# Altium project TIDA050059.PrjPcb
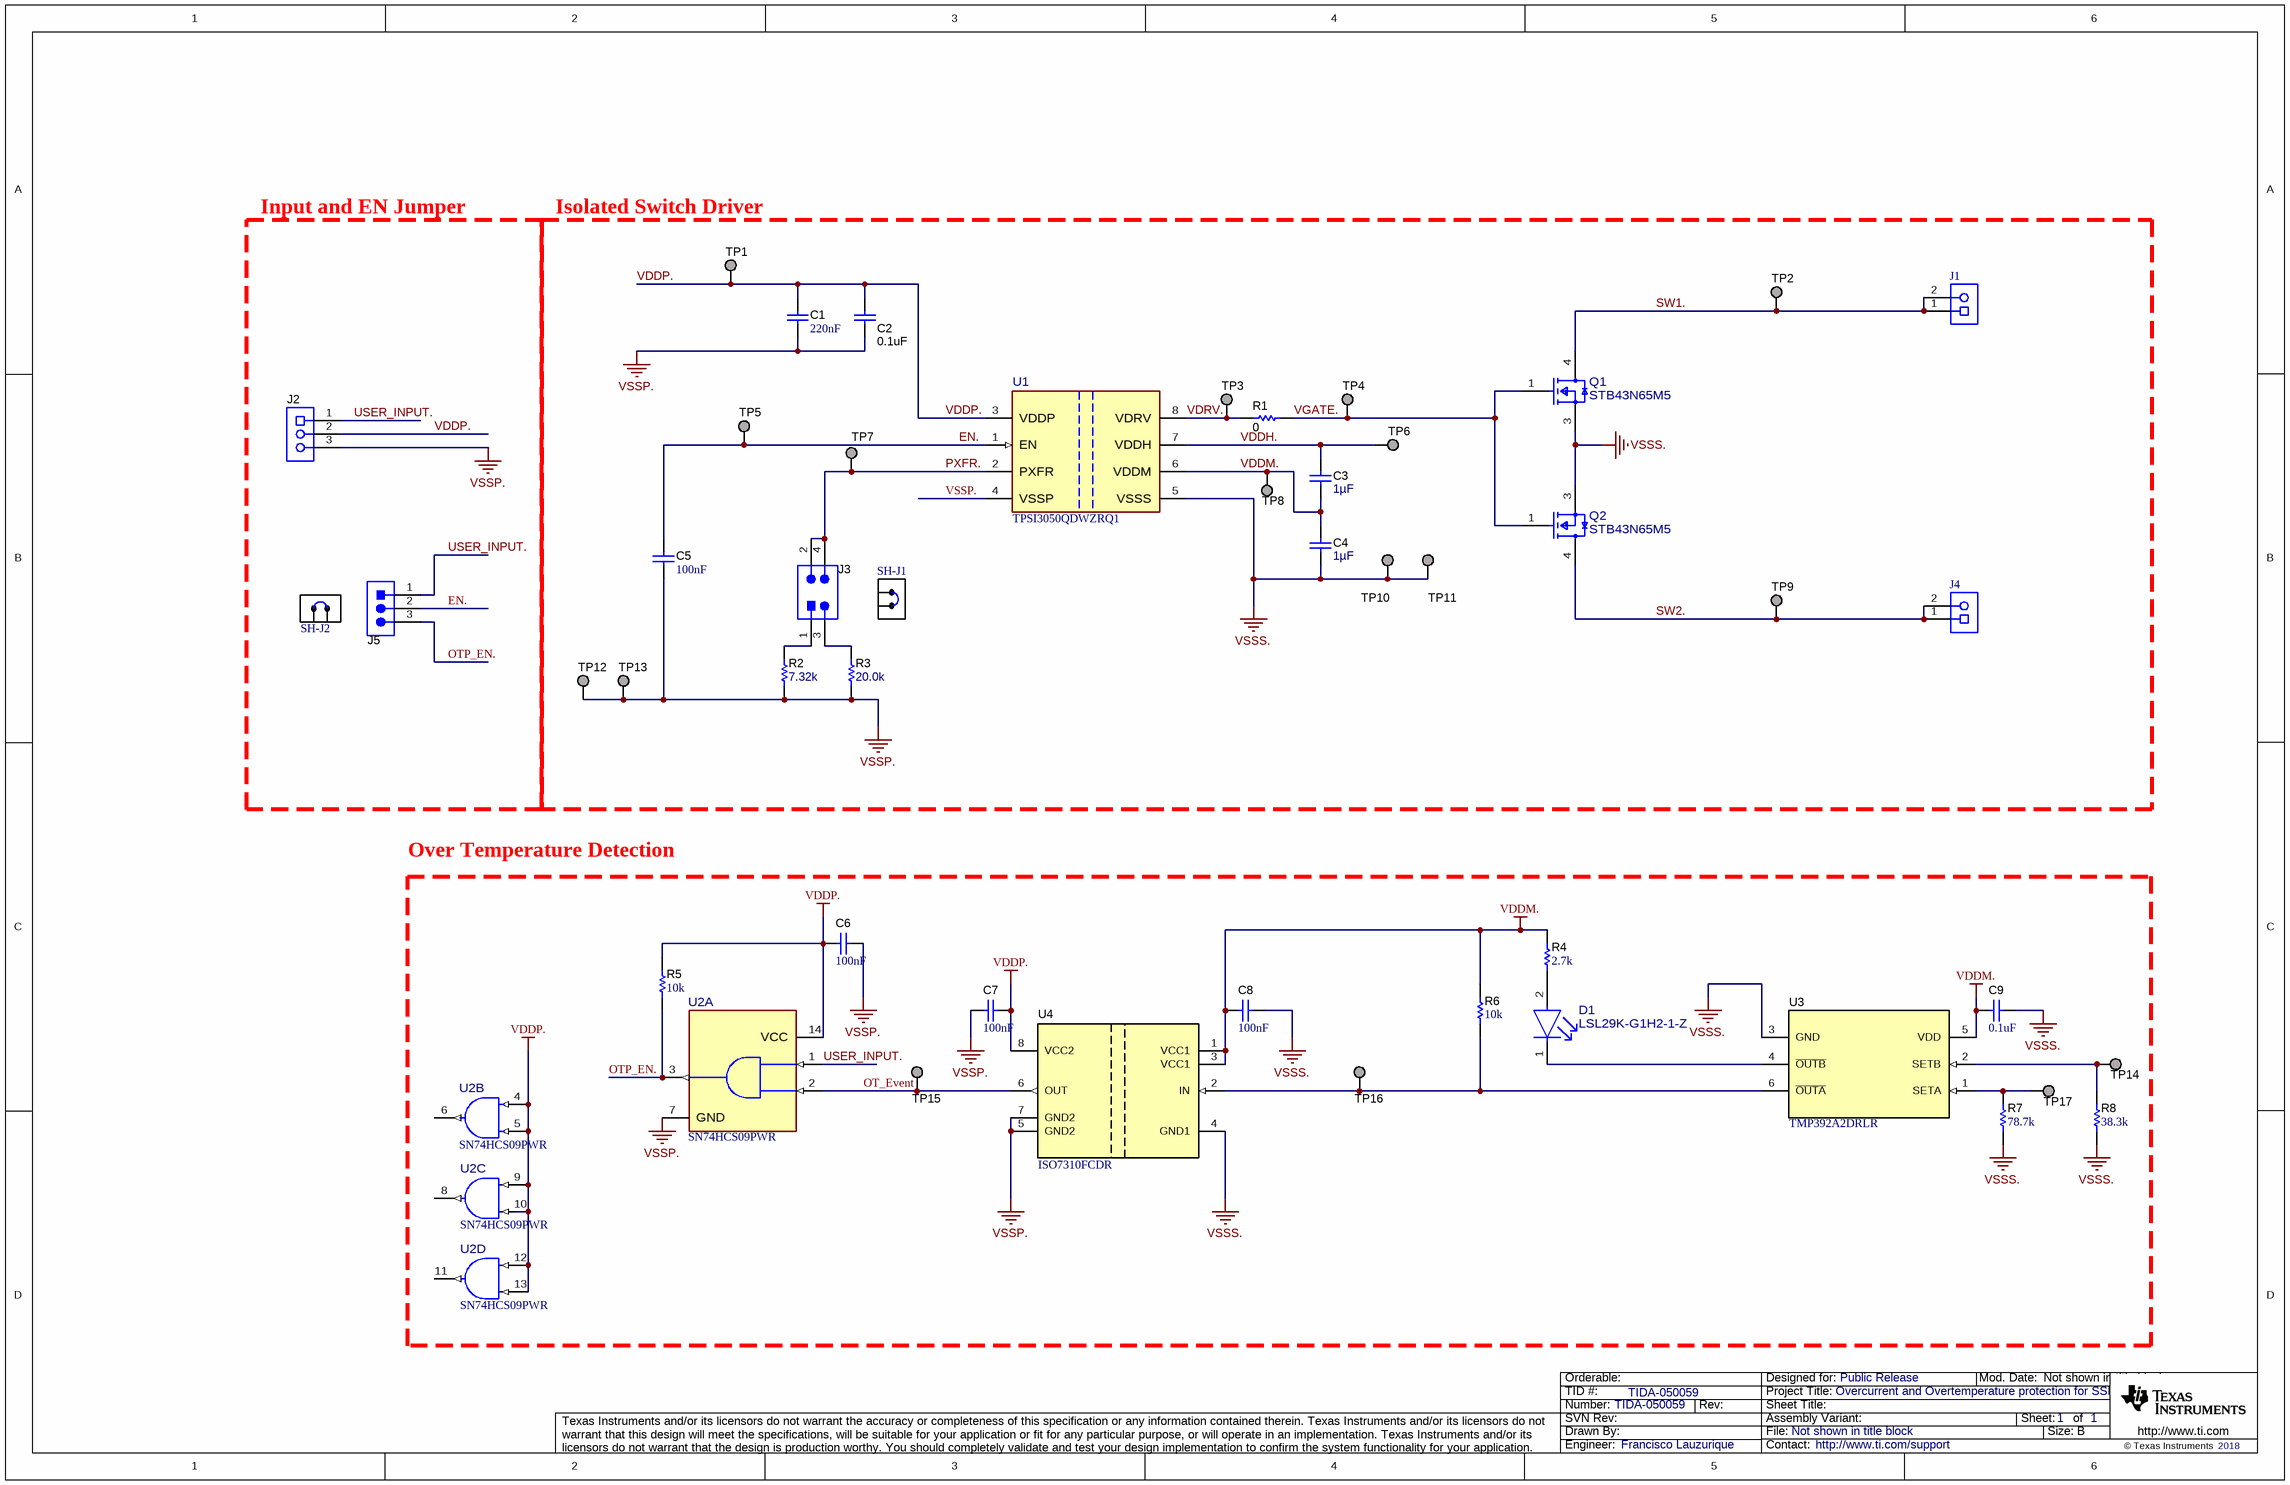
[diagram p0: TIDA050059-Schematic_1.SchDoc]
TID: TIDA-050059; TechSupport: http://www.ti.com/support; PRJ_Title: Overcurrent and Overtemperature protection for SSR; PRJ_Number: TIDA-050059; PRJ_Engineer: Francisco Lauzurique; PRJ_Customer: Public Release; PCB_Rev: E1; PCB_Layout: Francisco Lauzurique; CopyrightYear: 2018
3 sheets, 126 parts. Net scope: global (net labels, ports and power ports of the same name join across sheets).
Board file: TIDA050059-PCB.PcbDoc
Sheets:
  TIDA050059-Schematic_1.SchDoc
  TIDA050059-Schematic_2.SchDoc
  TIDA050059-Hardware.SchDoc

## Sheet TIDA050059-Schematic_1.SchDoc
size 431 x 279 mm; Date: Not shown in title block; ApprovedBy: Not shown in title block; CheckedBy: Not shown in title block; Author: Not shown in title block; CompanyName: Not shown in title block; Engineer: Not shown in title block; Organization: Not shown in title block; Address1: Not shown in title block; Address2: Not shown in title block; Address3: Not shown in title block; Address4: Not shown in title block; DocumentNumber: 1; Revision: Use project parameter SCH_Rev; SheetNumber: 1; SheetTotal: 1; PageSetup: Record=PageOptions¦CenterHorizontal=True¦CenterVertical=True¦PrintScale=1.00¦XCorrection=1.00¦YCorrection=1.00¦PrintKind=0¦BorderSize=5000000¦LeftOffset=0¦BottomOffset=0¦Orientation=2¦PaperLength=1000¦PaperWidth=1000¦Scale=100¦PaperSource=15¦PrintQuality=600¦MediaType=1¦DitherType=10¦PaperKind=Letter¦PrintScaleMode=1

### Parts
C1  Cap_F: 220nF  [0603]  (hidden comment: GRM188R71E224KA88D)
C2  ValueDisplayed: 0.1uF  [0402]  (hidden comment: GRM155R71E104KE14D)
C3  Cap_F: 1µF  [0603]  (hidden comment: UMK107AB7105KA-T)
C4  Cap_F: 1µF  [0603]  (hidden comment: UMK107AB7105KA-T)
C5  Cap_F: 100nF  [0805_HV]  (hidden comment: C0805C104K1RACTU)
C6  Cap_F: 100nF  [0603]  (hidden comment: GCM188R71E104KA57D)
C7  Cap_F: 100nF  [0603]  (hidden comment: GCM188R71E104KA57D)
C8  Cap_F: 100nF  [0603]  (hidden comment: GCM188R71E104KA57D)
C9  ValueDisplayed: 0.1uF  [0402]  (hidden comment: GRM155R71E104KE14D)
D1  LSL29K-G1H2-1-Z  [FP-LSL29K-G1H2-1-Z_0603-0]
J1  0393570002  [MOLEX_39357-0002]  (value not drawn)
J2  0393570003  [MOLEX_39357-0003]  (value not drawn)
J3  PBC02DAAN  [Sullins_PxC02DAAN]  (value not drawn)
J4  0393570002  [MOLEX_39357-0002]  (value not drawn)
J5  PEC03SAAN  [CONN_PEC03SAAN]  (value not drawn)
Q1  STB43N65M5  [FP-STB43N65M5_D2PAK-MFG]
Q2  STB43N65M5  [FP-STB43N65M5_D2PAK-MFG]
R1  ValueDisplayed: 0  [0603]  (hidden comment: ERJ-3GEY0R00V)
R2  ValueDisplayed: 7.32k  [0603]  (hidden comment: CRCW06037K32FKEA)
R3  ValueDisplayed: 20.0k  [0603]  (hidden comment: CRCW060320K0FKEA)
R4  ValueDisplayed: 2.7k  [0402]  (hidden comment: CRCW04022K70JNED)
R5  ValueDisplayed: 10k  [0603]  (hidden comment: CRCW060310K0JNEA)
R6  ValueDisplayed: 10k  [0603]  (hidden comment: CRCW060310K0JNEA)
R7  ValueDisplayed: 78.7k  [0402]  (hidden comment: CRCW040278K7FKED)
R8  ValueDisplayed: 38.3k  [0402]  (hidden comment: CRCW040238K3FKED)
SH-J1  SNT-100-BK-G  [SNT-100-BK-G]  (value not drawn)
SH-J2  SNT-100-BK-G  [SNT-100-BK-G]  (value not drawn)
TP1  5019  [Keystone_5019]  (value not drawn)
TP2  5019  [Keystone_5019]  (value not drawn)
TP3  5019  [Keystone_5019]  (value not drawn)
TP4  5019  [Keystone_5019]  (value not drawn)
TP5  5019  [Keystone_5019]  (value not drawn)
TP6  5019  [Keystone_5019]  (value not drawn)
TP7  5019  [Keystone_5019]  (value not drawn)
TP8  5019  [Keystone_5019]  (value not drawn)
TP9  5019  [Keystone_5019]  (value not drawn)
TP10  5019  [Keystone_5019]  (value not drawn)
TP11  5019  [Keystone_5019]  (value not drawn)
TP12  5019  [Keystone_5019]  (value not drawn)
TP13  5019  [Keystone_5019]  (value not drawn)
TP14  5019  [Keystone_5019]  (value not drawn)
TP15  5019  [Keystone_5019]  (value not drawn)
TP16  5019  [Keystone_5019]  (value not drawn)
TP17  5019  [Keystone_5019]  (value not drawn)
U1  TPSI3050QDWZRQ1  [DWZ0008A-MFG]
U2  SN74HCS09PWR  [PW0014A-MFG]  (parts A,B,C,D of 4)
U3  TMP392A2DRLR  [DRL0006A]
U4  ISO7310FCDR  [D0008B_L]

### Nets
VDDM.: C3.2 C4.1 C8.2 C9.2 R4.2 R6.2 TP8.1 U1.6(VDDM) U3.5(VDD) U4.1(VCC1) U4.3(VCC1)
VDDP.: C1.1 C2.1 C6.1 C7.1 J2.2 R5.2 TP1.1 U1.3(VDDP) U2.4(2A) U2.5(2B) U2.9(3A) U2.10(3B) U2.12(4A) U2.13(4B) U2.14(VCC) U4.8(VCC2)
VSSP.: C1.2 C2.2 C5.2 C6.2 C7.2 J2.3 R2.1 R3.1 TP12.1 TP13.1 U1.4(VSSP) U2.7(GND) U4.5(GND2) U4.7(GND2)
VSSS.: C4.2 C8.1 C9.1 Q1.3(S) Q2.3(S) R7.1 R8.1 TP10.1 TP11.1 U1.5(VSSS) U3.3(GND) U4.4(GND1)
EN.: C5.1 J5.2 TP5.1 U1.1(EN)
OT_Event: TP15.1 U2.2(1B) U4.6(OUT)
OTP_EN.: J5.3 R5.1 U2.3(1Y)
PXFR.: J3.2 J3.4 TP7.1 U1.2(PXFR)
SW1.: J1.1 J1.2 Q1.4(D) TP2.1
SW2.: J4.1 J4.2 Q2.4(D) TP9.1
USER_INPUT.: J2.1 J5.1 U2.1(1A)
VDDH.: C3.1 TP6.1 U1.7(VDDH)
VDRV.: R1.1 TP3.1 U1.8(VDRV)
VGATE.: Q1.1(G) Q2.1(G) R1.2 TP4.1
NetD1_1: D1.1(CATHODE) U3.4(~{OUTB})
NetD1_2: D1.2(ANODE) R4.1
NetJ3_1: J3.1 R2.2
NetJ3_3: J3.3 R3.2
NetR6_1: R6.1 TP16.1 U3.6(~{OUTA}) U4.2(IN)
NetR7_2: R7.2 TP17.1 U3.1(SETA)
NetR8_2: R8.2 TP14.1 U3.2(SETB)

Not connected (* = marked no-connect by the designer): U2 6(2Y) 8(3Y) 11(4Y)

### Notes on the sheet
- Input and EN Jumper
- (near TP1) Isolated Switch Driver
- Over Temperature Detection

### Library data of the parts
C1 = CMP-0007415-4: CAP, CERM, 0.22 uF, 25 V, +/- 10%, X7R, 0603; Manufacturer: MuRata; TaMin_C: -55°C; Polarized: N; SizeAreaWB_mm2: 4.68; Value1: Unknown; U/M: EA; Value: 0.22uF; TaMax_C: 125°C; SizeZ_mm: 1; SizeX_mm: 1.6; SizeY_mm: 0.8; Value2: 25V; SizeArea_mm2: 1.28; AEC Category: Q200
C2 = CMP-0006659-2: CAP, CERM, 0.1 uF, 25 V, +/- 10%, X7R, 0402; Manufacturer: MuRata; TaMin_C: -55°C; Polarized: N; SizeAreaWB_mm2: 3; Value1: Unknown; U/M: EA; Value: 0.1uF; TaMax_C: 125°C; SizeZ_mm: 0.6; SizeX_mm: 1; SizeY_mm: 0.5; Value2: 25V; CompType: Capacitor; Cap_F: 100nF; AEC Category: Q200
C3 C4 = CMP-0007508-5: CAP, CERM, 1 uF, 50 V, +/- 10%, X7R, 0603; Manufacturer: Taiyo Yuden; TaMin_C: -55°C; Polarized: N; SizeAreaWB_mm2: 4.68; Value1: Unknown; U/M: EA; Value: 1uF; TaMax_C: 125°C; SizeZ_mm: 1; SizeX_mm: 1.6; SizeY_mm: 0.8; Value2: 50V; SizeArea_mm2: 1.28; AEC Category: Q200
C5 = CMP-0007722-2: CAP, CERM, 0.1 uF, 100 V, +/- 10%, X7R, 0805; Manufacturer: Kemet; TaMin_C: -55°C; ESR_ohm: 64m; Polarized: N; SizeAreaWB_mm2: 6.75; Value1: 0.064 ohm; U/M: EA; Value: 0.1uF; TaMax_C: 125°C; SizeZ_mm: 1.45; SizeX_mm: 2; SizeY_mm: 1.25; Cap_Case: 0805; Value2: 100V; SizeArea_mm2: 2.5; IRMS_A: 1.64A; AEC Category: Q200
C6-C8 = CMP-0084679-1: CAP, CERM, 0.1 µF, 25 V,+/- 10%, X7R, AEC-Q200 Grade 1, 0603; Manufacturer: MuRata; VDC_V: 25V; TaMin_C: -55°C; SizeY_mm: 0.8; Polarized: N; SizeArea_mm2: 1.28; SizeZ_mm: 1; SizeX_mm: 1.6; AEC Qualified: Y; AEC Category: Q200; Value: 0.1uF; ValueDisplayed: 0.1µF; TaMax_C: 125°C; U/M: EA; SizeAreaWB_mm2: 4.68
C9 = CMP-0006659-2: CAP, CERM, 0.1 uF, 25 V, +/- 10%, X7R, 0402; Manufacturer: MuRata; TaMin_C: -55°C; Polarized: N; SizeAreaWB_mm2: 3; Value1: Unknown; U/M: EA; Value: 0.1uF; TaMax_C: 125°C; SizeZ_mm: 0.6; SizeX_mm: 1; SizeY_mm: 0.5; Value2: 25V; Cap_F: 100nF; AEC Category: Q200
D1 = CMP-0092845-1: LED Uni-Color Red 643nm 2-Pin Chip 0603(1608Metric) T/R; Manufacturer: OSRAM Opto Semiconductors; AEC Grade: Grade 2; LuminousFlux_PhiV: 8.1/16.1lm; Vf_V: 1.8V; Forward Current: 2mA; Led Orientation: Top View; SizeZ_mm: 0.67mm; AEC Qualified: Yes; Luminous Intensity: 1.8-2.24/3.55-4.5mcd; Vr_V: 12V; Angle: 160°; LambdaD: 630nm; Tjmax_C: 110°C
J1 J4 = CMP-0055341-2: Terminal Block, 3.5 mm, 2x1, Tin, TH; Manufacturer: Molex; CNHeader: FALSE; CT: TRUE; Green_Lifecycle: Not Set; Green_REACh: Incomplete
J2 = CMP-0055340-2: Terminal Block, 3.5 mm, 3x1, Tin, TH; Manufacturer: Molex; CNHeader: FALSE; CT: TRUE; Green_REACh: Incomplete; Green_Lifecycle: Not Set
J3 = CMP-0054598-1: Header, 2.54mm, 2x2, Gold, TH; Manufacturer: Sullins Connector Solutions; CNHeader: TRUE; Current_A: 3A; Shrouded: N; Gender: Male; Voltage_V: 1.8kV; Row_Count: 2; RowSpacing_mm: 2.54; CT: FALSE; Cert_UL: Y
J5 = CMP-0002338-1: Header, 100mil, 3x1, Tin, TH; Manufacturer: Sullins Connector Solutions; CNHeader: TRUE; Current_A: 3A; Green_Lifecycle: Not Set; Shrouded: N; Gender: Male; Green_REACh: Incomplete; Voltage_V: 1.8kV; Row_Count: 1; Pitch_mm: 2.54; CT: FALSE; Cert_UL: Y
Q1 Q2 = CMP-0088026-1: MOSFET N-CH 650V 42A; Manufacturer: STMicroelectronics; Rdson45_ohm: 0.058; SizeZ_mm: 4.83mm; AEC Qualified: Yes; ChMode: False; Vgs_V: 25V; QgTyp_nC: 100nC @ 10V
R1 = CMP-0025874-4: RES, 0, 5%, 0.1 W, AEC-Q200 Grade 0, 0603; Manufacturer: Panasonic; Power_W: 100mW; TempCo: 600 ppm/C; Value_Code: 0000; Value: 0; EIA_Code: E24; SizeX_mm: 1.6; SizeY_mm: 0.8; SizeZ_mm: 1; Value2: 0.1W; SizeArea_mm2: 1.28; AEC Qualified: Y; VDC_V: 50V; AEC Category: Q200; SizeAreaWB_mm2: 4.68
R2 = CMP-0022600-4: RES, 7.32 k, 1%, 0.1 W, AEC-Q200 Grade 0, 0603; Manufacturer: Vishay-Dale; Power_W: 100mW; TempCo: 100 ppm/C; Value_Code: 7k32; Value: 7.32k; EIA_Code: E96; SizeX_mm: 1.6; SizeY_mm: 0.8; SizeZ_mm: 1; Value2: 0.1W; SizeArea_mm2: 1.28; AEC Qualified: Y; VDC_V: 75V; AEC Category: Q200; AEC Grade: 0
R3 = CMP-0022204-4: RES, 20.0 k, 1%, 0.1 W, AEC-Q200 Grade 0, 0603; Manufacturer: Vishay-Dale; Power_W: 100mW; TempCo: 100 ppm/C; Value_Code: 20k0; Value: 20.0k; EIA_Code: E96; Res_ohm: 20k; SizeX_mm: 1.6; SizeY_mm: 0.8; SizeZ_mm: 1; Value2: 0.1W; SizeArea_mm2: 1.28; AEC Qualified: Y; VDC_V: 75V; AEC Category: Q200; AEC Grade: 0
R4 = CMP-0026892-5: RES, 2.7 k, 5%, 0.063 W, AEC-Q200 Grade 0, 0402; Manufacturer: Vishay-Dale; Power_W: 63mW; TempCo: 200 ppm/C; Value_Code: 2k70; Value: 2.7k; EIA_Code: E24; SizeX_mm: 1; SizeY_mm: 0.5; SizeZ_mm: 0.6; Value2: 0.063W; AEC Qualified: Y; VDC_V: 50V; AEC Category: Q200; AEC Grade: 0
R5 R6 = CMP-0025701-4: RES, 10 k, 5%, 0.1 W, AEC-Q200 Grade 0, 0603; Manufacturer: Vishay-Dale; Power_W: 100mW; TempCo: 200 ppm/C; Value_Code: 10k0; Value: 10k; EIA_Code: E24; SizeX_mm: 1.6; SizeY_mm: 0.8; SizeZ_mm: 1; Value2: 0.1W; SizeArea_mm2: 1.28; AEC Qualified: Y; VDC_V: 75V; AEC Category: Q200; AEC Grade: 0
R7 = CMP-0026551-2: RES, 78.7 k, 1%, 0.063 W, AEC-Q200 Grade 0, 0402; Manufacturer: Vishay-Dale; Power_W: 63mW; TempCo: 100 ppm/C; Value_Code: 78k7; Value: 78.7k; EIA_Code: E96; SizeX_mm: 1; SizeY_mm: 0.5; SizeZ_mm: 0.6; Value2: 0.063W; AEC Qualified: Y; VDC_V: 50V; AEC Category: Q200; AEC Grade: 0
R8 = CMP-0026323-2: RES, 38.3 k, 1%, 0.063 W, AEC-Q200 Grade 0, 0402; Manufacturer: Vishay-Dale; Power_W: 63mW; TempCo: 100 ppm/C; Value_Code: 38k3; Value: 38.3k; EIA_Code: E96; SizeX_mm: 1; SizeY_mm: 0.5; SizeZ_mm: 0.6; Value2: 0.063W; AEC Qualified: Y; VDC_V: 50V; AEC Category: Q200; AEC Grade: 0
SH-J1 SH-J2 = CMP-0003623-3: Shunt, 100mil, Gold plated, Black; Alternate PartNumber: 969102-0000-DA; Manufacturer: Samtec; Alternate Manufacturer: 3M; Value: 1x2
TP1-TP17 = CMP-0055162-1: Test Point, Miniature, SMT; Manufacturer: Keystone; CNHeader: FALSE; Green_Lifecycle: Active; Green_REACh: Passed; CT: TRUE
U1 = CMP-0095183-1: Automotive Reinforced Isolated Switch Driver With Integrated 10-V Gate Supply; Manufacturer: Texas Instruments; Min Supply Voltage: 3V; TJmax_C: +150°C; Output Voltage: 10V; AEC Qualified: Yes; Standoff Height: 0.36mm; Rise Time: 5ns; SizeZ_mm: 2.8mm; Number Of Drivers: 1; Max Supply Voltage: 5.5V; AEC Grade: Grade 1; TaMax_C: +125°C; Nominal Supply Current: 4-33mA; TaMin_C: -40°C
U2 = CMP-0092187-1: AND Gate IC 4 Channel Schmitt Trigger, Open Drain 14-TSSOP; Manufacturer: Texas Instruments; TaMax_C: +125°C; Number Of Inputs: 2; PositionCount: 4; Standoff Height: 0.05mm; SizeZ_mm: 1.2mm; TaMin_C: -55°C; TJmax_C: +150°C; Nominal Supply Current: 0.1uA; Propagation Delay: 9ns; Min Supply Voltage: 2V; Max Supply Voltage: 6V; Number Of Outputs: 1; AEC Qualified: No
U3 = CMP-0860529-1: Ultra-Small, Dual-Channel, 0.5-μA, Resistor-Programmable Temperature Switch, DRL0006A (SOT-5X3-6); Alternate Manufacturer: Texas Instruments; SizeZ_mm: 0.6; SizeAreaWB_mm2: 6.76; SizeY_mm: 1.6; SizeArea_mm2: 2.56; CompType: IC; AEC Category: Q200; AEC Qualified: N
U4 = CMP-0076045-1: Robust EMC, Low Power Single-Channel 1/0 Digital Isolator, Fail-safe Low, D0008B (SOIC-8); Manufacturer: Texas Instruments; SizeAreaWB_mm2: 55.2; SizeArea_mm2: 29.4; SizeZ_mm: 1.75; SizeY_mm: 4.9; U/M: EA; CompType: IC; SizeX_mm: 6.0

## Sheet TIDA050059-Schematic_2.SchDoc
size 431 x 279 mm; Date: Not shown in title block; ApprovedBy: Not shown in title block; CheckedBy: Not shown in title block; Author: Not shown in title block; CompanyName: Not shown in title block; Engineer: Not shown in title block; Organization: Not shown in title block; Address1: Not shown in title block; Address2: Not shown in title block; Address3: Not shown in title block; Address4: Not shown in title block; DocumentNumber: 1; Revision: Use project parameter SCH_Rev; SheetNumber: 1; SheetTotal: 1; PageSetup: Record=PageOptions¦CenterHorizontal=True¦CenterVertical=True¦PrintScale=1.00¦XCorrection=1.00¦YCorrection=1.00¦PrintKind=0¦BorderSize=5000000¦LeftOffset=0¦BottomOffset=0¦Orientation=2¦PaperLength=1000¦PaperWidth=1000¦Scale=100¦PaperSource=15¦PrintQuality=600¦MediaType=1¦DitherType=10¦PaperKind=Letter¦PrintScaleMode=1
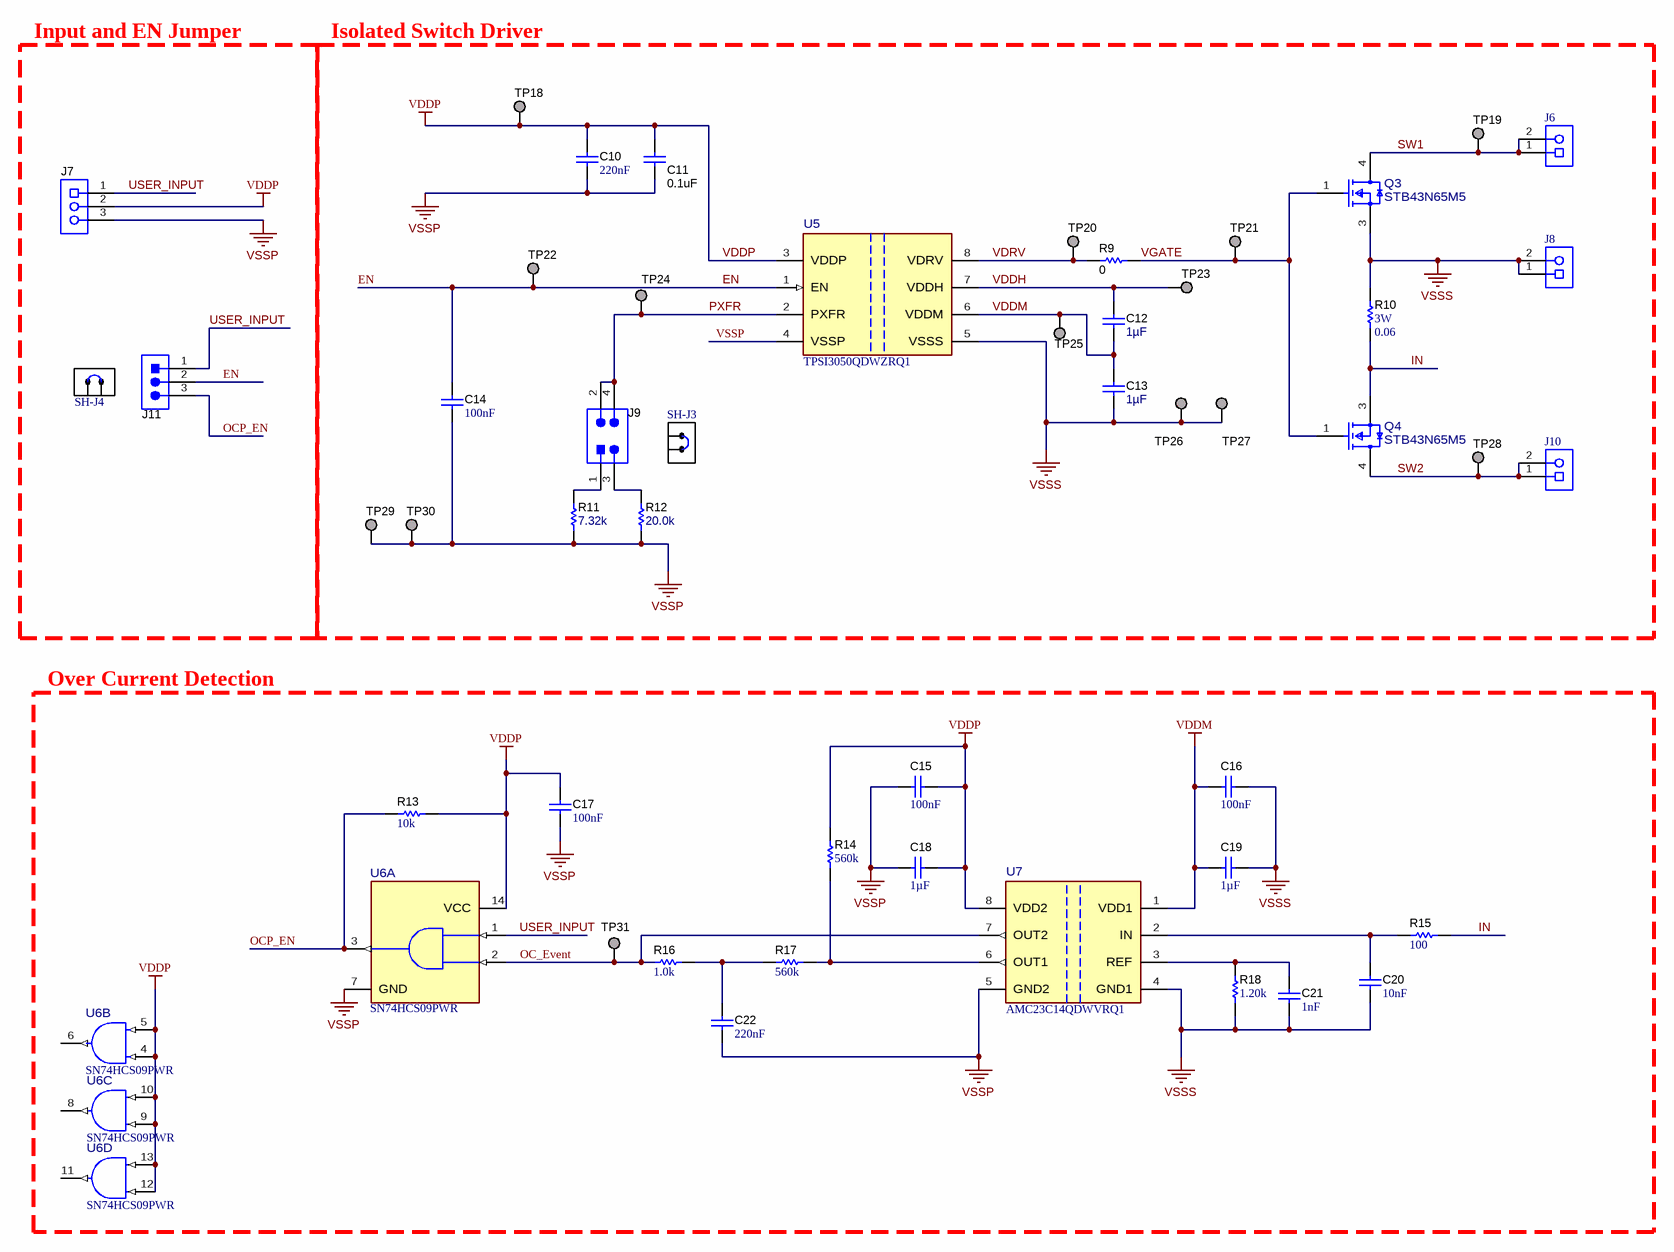
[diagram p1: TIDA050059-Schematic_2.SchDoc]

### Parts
C10  Cap_F: 220nF  [0603]  (hidden comment: GRM188R71E224KA88D)
C11  ValueDisplayed: 0.1uF  [0402]  (hidden comment: GRM155R71E104KE14D)
C12  Cap_F: 1µF  [0603]  (hidden comment: UMK107AB7105KA-T)
C13  Cap_F: 1µF  [0603]  (hidden comment: UMK107AB7105KA-T)
C14  Cap_F: 100nF  [0805_HV]  (hidden comment: C0805C104K1RACTU)
C15  Cap_F: 100nF  [0603]  (hidden comment: GCM188R71E104KA57D)
C16  Cap_F: 100nF  [0603]  (hidden comment: GCM188R71E104KA57D)
C17  Cap_F: 100nF  [0603]  (hidden comment: GCM188R71E104KA57D)
C18  Cap_F: 1µF  [0603]  (hidden comment: GCM188R71E105KA64D)
C19  Cap_F: 1µF  [0603]  (hidden comment: GCM188R71E105KA64D)
C20  Cap_F: 10nF  [0603]  (hidden comment: C1608X7R1H103K080AA)
C21  Cap_F: 1nF  [0603]  (hidden comment: C0603C102J5RACTU)
C22  Cap_F: 220nF  [0603]  (hidden comment: CGA3E3X7R1H224K080AB)
J6  0393570002  [MOLEX_39357-0002]  (value not drawn)
J7  0393570003  [MOLEX_39357-0003]  (value not drawn)
J8  0393570002  [MOLEX_39357-0002]  (value not drawn)
J9  PBC02DAAN  [Sullins_PxC02DAAN]  (value not drawn)
J10  0393570002  [MOLEX_39357-0002]  (value not drawn)
J11  PEC03SAAN  [CONN_PEC03SAAN]  (value not drawn)
Q3  STB43N65M5  [FP-STB43N65M5_D2PAK-MFG]
Q4  STB43N65M5  [FP-STB43N65M5_D2PAK-MFG]
R9  ValueDisplayed: 0  [0603]  (hidden comment: ERJ-3GEY0R00V)
R10  Value2: 3W  ValueDisplayed: 0.06  [2512]  (hidden comment: NA)
R11  ValueDisplayed: 7.32k  [0603]  (hidden comment: CRCW06037K32FKEA)
R12  ValueDisplayed: 20.0k  [0603]  (hidden comment: CRCW060320K0FKEA)
R13  ValueDisplayed: 10k  [0603]  (hidden comment: CRCW060310K0JNEA)
R14  ValueDisplayed: 560k  [0603]  (hidden comment: CRCW0603560KFKEA)
R15  ValueDisplayed: 100  [0603]  (hidden comment: RMCP0603JT100R)
R16  ValueDisplayed: 1.0k  [0603]  (hidden comment: CRCW06031K00JNEA)
R17  ValueDisplayed: 560k  [0603]  (hidden comment: CRCW0603560KFKEA)
R18  ValueDisplayed: 1.20k  [0603]  (hidden comment: RC0603FR-071K2L)
SH-J3  SNT-100-BK-G  [SNT-100-BK-G]  (value not drawn)
SH-J4  SNT-100-BK-G  [SNT-100-BK-G]  (value not drawn)
TP18  5019  [Keystone_5019]  (value not drawn)
TP19  5019  [Keystone_5019]  (value not drawn)
TP20  5019  [Keystone_5019]  (value not drawn)
TP21  5019  [Keystone_5019]  (value not drawn)
TP22  5019  [Keystone_5019]  (value not drawn)
TP23  5019  [Keystone_5019]  (value not drawn)
TP24  5019  [Keystone_5019]  (value not drawn)
TP25  5019  [Keystone_5019]  (value not drawn)
TP26  5019  [Keystone_5019]  (value not drawn)
TP27  5019  [Keystone_5019]  (value not drawn)
TP28  5019  [Keystone_5019]  (value not drawn)
TP29  5019  [Keystone_5019]  (value not drawn)
TP30  5019  [Keystone_5019]  (value not drawn)
TP31  5019  [Keystone_5019]  (value not drawn)
U5  TPSI3050QDWZRQ1  [DWZ0008A-MFG]
U6  SN74HCS09PWR  [PW0014A-MFG]  (parts A,B,C,D of 4)
U7  AMC23C14QDWVRQ1  [DWV0008A-MFG]

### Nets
VDDM: C12.2 C13.1 C16.2 C19.2 TP25.1 U5.6(VDDM) U7.1(VDD1)
VDDP: C10.1 C11.1 C15.1 C17.1 C18.1 J7.2 R13.2 R14.2 TP18.1 U5.3(VDDP) U6.4(2A) U6.5(2B) U6.9(3A) U6.10(3B) U6.12(4A) U6.13(4B) U6.14(VCC) U7.8(VDD2)
VSSP: C10.2 C11.2 C14.2 C15.2 C17.2 C18.2 C22.2 J7.3 R11.1 R12.1 TP29.1 TP30.1 U5.4(VSSP) U6.7(GND) U7.5(GND2)
VSSS: C13.2 C16.1 C19.1 C20.2 C21.2 J8.1 J8.2 Q3.3(S) R10.2 R18.1 TP26.1 TP27.1 U5.5(VSSS) U7.4(GND1)
EN: C14.1 J11.2 TP22.1 U5.1(EN)
IN: Q4.3(S) R10.1 R15.2
OC_Event: R16.1 TP31.1 U6.2(1B) U7.7(OUT2)
OCP_EN: J11.3 R13.1 U6.3(1Y)
PXFR: J9.2 J9.4 TP24.1 U5.2(PXFR)
SW1: J6.1 J6.2 Q3.4(D) TP19.1
SW2: J10.1 J10.2 Q4.4(D) TP28.1
USER_INPUT: J7.1 J11.1 U6.1(1A)
VDDH: C12.1 TP23.1 U5.7(VDDH)
VDRV: R9.1 TP20.1 U5.8(VDRV)
VGATE: Q3.1(G) Q4.1(G) R9.2 TP21.1
NetC20_1: C20.1 R15.1 U7.2(IN)
NetC21_1: C21.1 R18.2 U7.3(REF)
NetC22_1: C22.1 R16.2 R17.1
NetJ9_1: J9.1 R11.2
NetJ9_3: J9.3 R12.2
NetR14_1: R14.1 R17.2 U7.6(OUT1)

Not connected (* = marked no-connect by the designer): U6 6(2Y) 8(3Y) 11(4Y)

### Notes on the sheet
- Input and EN Jumper
- Isolated Switch Driver
- Over Current Detection

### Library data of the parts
C10 = CMP-0007415-4: as C1 on sheet TIDA050059-Schematic_1
C11 = CMP-0006659-2: as C2 on sheet TIDA050059-Schematic_1
C12 C13 = CMP-0007508-5: as C3 on sheet TIDA050059-Schematic_1
C14 = CMP-0007722-2: as C5 on sheet TIDA050059-Schematic_1
C15-C17 = CMP-0084679-1: as C6 on sheet TIDA050059-Schematic_1
C18 C19 = CMP-0007139-4: CAP, CERM, 1 uF, 25 V, +/- 10%, X7R, AEC-Q200 Grade 1, 0603; Manufacturer: MuRata; TaMin_C: -55°C; Polarized: N; SizeAreaWB_mm2: 4.68; Value1: Unknown; U/M: EA; Value: 1uF; TaMax_C: 125°C; SizeZ_mm: 1; SizeX_mm: 1.6; SizeY_mm: 0.8; Value2: 25V; SizeArea_mm2: 1.28; AEC Qualified: Y; AEC Category: Q200
C20 = CMP-0007043-4: CAP, CERM, 0.01 uF, 50 V, +/- 10%, X7R, 0603; Manufacturer: TDK; TaMin_C: -55°C; ESR_ohm: 53.9m; Polarized: N; SizeAreaWB_mm2: 4.68; Value1: 0.0539 ohm; U/M: EA; Value: 0.01uF; TaMax_C: 125°C; SizeZ_mm: 1; SizeX_mm: 1.6; SizeY_mm: 0.8; Value2: 50V; SizeArea_mm2: 1.28; AEC Category: Q200
C21 = CMP-0006845-4: CAP, CERM, 1000 pF, 50 V, +/- 5%, X7R, 0603; Manufacturer: Kemet; TaMin_C: -55°C; Polarized: N; SizeAreaWB_mm2: 4.68; Value1: Unknown; U/M: EA; Value: 1000pF; TaMax_C: 125°C; SizeZ_mm: 1; SizeX_mm: 1.6; SizeY_mm: 0.8; Value2: 50V; SizeArea_mm2: 1.28; AEC Category: Q200
C22 = CMP-0007094-5: CAP, CERM, 0.22 uF, 50 V, +/- 10%, X7R, AEC-Q200 Grade 1, 0603; Manufacturer: TDK; TaMin_C: -55°C; ESR_ohm: 21.699m; Polarized: N; SizeAreaWB_mm2: 4.68; Value1: 0.021699 ohm; U/M: EA; Value: 0.22uF; TaMax_C: 125°C; SizeZ_mm: 1; SizeX_mm: 1.6; SizeY_mm: 0.8; Value2: 50V; SizeArea_mm2: 1.28; AEC Qualified: Y; IRMS_A: 1.125A; AEC Category: Q200
J6 J8 J10 = CMP-0055341-2: as J1 on sheet TIDA050059-Schematic_1
J7 = CMP-0055340-2: as J2 on sheet TIDA050059-Schematic_1
J9 = CMP-0054598-1: as J3 on sheet TIDA050059-Schematic_1
J11 = CMP-0002338-1: as J5 on sheet TIDA050059-Schematic_1
Q3 Q4 = CMP-0088026-1: as Q1 on sheet TIDA050059-Schematic_1
R9 = CMP-0025874-4: as R1 on sheet TIDA050059-Schematic_1
R10 = CMP-0015413-2: RES, 0.01, 1%, 1 W, 2512; Manufacturer: CTS Resistor; PartNumber: 73M1R010F; Power_W: 1W; TempCo: 100 ppm/C; Value_Code: R010; U/M: EA; Value: 0.01; EIA_Code: E96; Res_ohm: 10m; SizeX_mm: 6.3; SizeY_mm: 3.2; SizeZ_mm: 0.71; SizeArea_mm2: 20.16; AEC Category: Q200
R11 = CMP-0022600-4: as R2 on sheet TIDA050059-Schematic_1
R12 = CMP-0022204-4: as R3 on sheet TIDA050059-Schematic_1
R13 = CMP-0025701-4: as R5 on sheet TIDA050059-Schematic_1
R14 R17 = CMP-0022496-4: RES, 560 k, 1%, 0.1 W, AEC-Q200 Grade 0, 0603; Manufacturer: Vishay-Dale; Power_W: 100mW; TempCo: 100 ppm/C; Value: 560k; SizeX_mm: 1.6; SizeY_mm: 0.8; SizeZ_mm: 1; Value2: 0.1W; SizeArea_mm2: 1.28; AEC Qualified: Y; VDC_V: 75V; AEC Grade: 0; AEC Category: Q200
R15 = CMP-0860543-1: RES, 100, 5%, 0.25 W, AEC-Q200 Grade 0, 0603; Manufacturer: Stackpole Electronics Inc; AEC Category: Q200; AEC Grade: 0; SizeAreaWB_mm2: 4.68; TempCo: 100 ppm/C; SizeY_mm: 0.8; AEC Qualified: Y; Value: 100; Value2: 0.25W; SizeX_mm: 1.6; SizeArea_mm2: 1.28; SizeZ_mm: 1; EIA_Code: E24; Power_W: 250mW; Value_Code: 100R
R16 = CMP-0025729-4: RES, 1.0 k, 5%, 0.1 W, AEC-Q200 Grade 0, 0603; Manufacturer: Vishay-Dale; Power_W: 100mW; TempCo: 200 ppm/C; Value_Code: 1k00; Value: 1.0k; EIA_Code: E24; Res_ohm: 1k; SizeX_mm: 1.6; SizeY_mm: 0.8; SizeZ_mm: 1; Value2: 0.1W; SizeArea_mm2: 1.28; AEC Qualified: Y; VDC_V: 75V; AEC Category: Q200; AEC Grade: 0
R18 = CMP-0022874-5: RES, 1.20 k, 1%, 0.1 W, 0603; Manufacturer: Yageo; Power_W: 100mW; TempCo: 100 ppm/C; Value_Code: 1k20; Value: 1.20k; Res_ohm: 1.2k; SizeX_mm: 1.6; SizeY_mm: 0.8; SizeZ_mm: 1; Value2: 0.1W; SizeArea_mm2: 1.28; AEC Qualified: N; VDC_V: 75V; AEC Category: Q200; SizeAreaWB_mm2: 4.68
SH-J3 SH-J4 = CMP-0003623-3: as SH-J1 on sheet TIDA050059-Schematic_1
TP18-TP31 = CMP-0055162-1: as TP1 on sheet TIDA050059-Schematic_1
U5 = CMP-0095183-1: as U1 on sheet TIDA050059-Schematic_1
U6 = CMP-0092187-1: as U2 on sheet TIDA050059-Schematic_1
U7 = CMP-0092425-3: Dual, Fast Response, Reinforced Isolated Window Comparator with Adjustable Threshold, SOICW8; Manufacturer: Texas Instruments; Min Supply Voltage: 2.7V; TJmax_C: +150°C; TaMax_C: +125°C; Input Bias Current: 0.00001uA; AEC Qualified: Yes; TaMin_C: -55°C; AEC Grade: Grade 1; Max Supply Voltage: 27V; Standoff Height: 0.36mm; AEC Category: Q200; SizeZ_mm: 2.8mm; CompType: IC; Number Of Channels: 2

## Sheet TIDA050059-Hardware.SchDoc
size 431 x 279 mm; Date: Not shown in title block; ApprovedBy: Not shown in title block; CheckedBy: Not shown in title block; Author: Not shown in title block; CompanyName: Not shown in title block; Engineer: Not shown in title block; Organization: Not shown in title block; Address1: Not shown in title block; Address2: Not shown in title block; Address3: Not shown in title block; Address4: Not shown in title block; DocumentNumber: 3; Revision: Use project parameter SCH_Rev; SheetNumber: 3; SheetTotal: 6; PageSetup: Record=PageOptions¦CenterHorizontal=True¦CenterVertical=True¦PrintScale=1.00¦XCorrection=1.00¦YCorrection=1.00¦PrintKind=0¦BorderSize=5000000¦LeftOffset=0¦BottomOffset=0¦Orientation=2¦PaperLength=1000¦PaperWidth=1000¦Scale=100¦PaperSource=15¦PrintQuality=600¦MediaType=1¦DitherType=10¦PaperKind=Letter¦PrintScaleMode=1
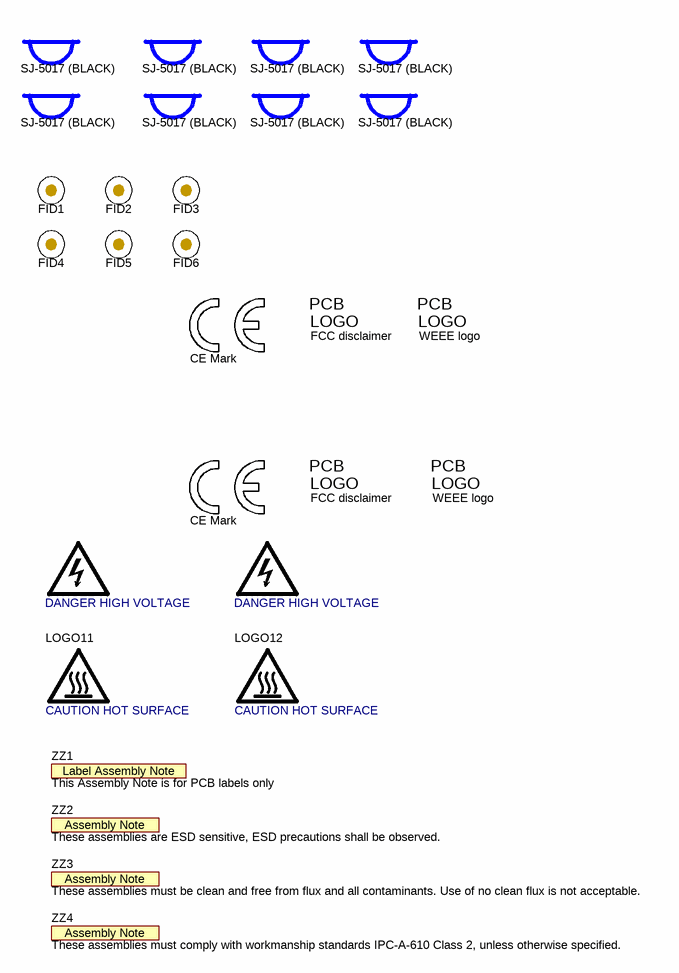
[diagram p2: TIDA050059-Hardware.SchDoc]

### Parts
FID1  Fiducial  [Fiducial10-20]  (value not drawn)
FID2  Fiducial  [Fiducial10-20]  (value not drawn)
FID3  Fiducial  [Fiducial10-20]  (value not drawn)
FID4  Fiducial  [Fiducial10-20]  (value not drawn)
FID5  Fiducial  [Fiducial10-20]  (value not drawn)
FID6  Fiducial  [Fiducial10-20]  (value not drawn)
H1  SJ-5017 (BLACK)  [3M_SJ-5017BLACK]
H2  SJ-5017 (BLACK)  [3M_SJ-5017BLACK]
H3  SJ-5017 (BLACK)  [3M_SJ-5017BLACK]
H4  SJ-5017 (BLACK)  [3M_SJ-5017BLACK]
H5  SJ-5017 (BLACK)  [3M_SJ-5017BLACK]
H6  SJ-5017 (BLACK)  [3M_SJ-5017BLACK]
H7  SJ-5017 (BLACK)  [3M_SJ-5017BLACK]
H8  SJ-5017 (BLACK)  [3M_SJ-5017BLACK]
Logo1  FCC disclaimer  [FCC_disclaimer]  (no BOM)
Logo2  WEEE logo  [WEEE_Minimum]  (no BOM)
Logo3  CE Mark  [CE_Mark_5mm]  (no BOM)
Logo5  FCC disclaimer  [FCC_disclaimer]  (no BOM)
Logo6  WEEE logo  [WEEE_Minimum]  (no BOM)
Logo7  CE Mark  [CE_Mark_5mm]  (no BOM)
LOGO9  DANGER HIGH VOLTAGE  [IEC_HighVoltage_Small]  (no BOM)
LOGO10  DANGER HIGH VOLTAGE  [IEC_HighVoltage_Small]  (no BOM)
LOGO11  CAUTION HOT SURFACE  [IEC_HotSurface_Small]  (no BOM)
LOGO12  CAUTION HOT SURFACE  [IEC_HotSurface_Small]  (no BOM)
ZZ1  This Assembly Note is for PCB labels only  [AssemblyNoteLabel]  (no BOM)
ZZ2  These assemblies are ESD sensitive, ESD precautions shall be observed.  [AssemblyNote]  (no BOM)
ZZ3  These assemblies must be clean and free from flux and all contaminants. Use of no clean flux is not acceptable.  [AssemblyNote]  (no BOM)
ZZ4  These assemblies must comply with workmanship standards IPC-A-610 Class 2, unless otherwise specified.  [AssemblyNote]  (no BOM)

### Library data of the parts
FID1-FID6 = CMP-0077181-1: Fiducial mark.  There is nothing to buy or mount.
H1-H8 = CMP-0003997-1: Bumpon, Cylindrical, 0.75 X 0.38 inch, Black; Manufacturer: 3M
Logo1 Logo5 = CMP-0074847-1: FCC_disclaimer; Library Reference: Logo
Logo2 Logo6 = CMP-0074769-1
Logo3 Logo7 = CMP-0074844-1: SymbolCreator: a0412235
LOGO9 LOGO10 = CMP-0074835-1: IEC 61010-1 High Voltage Warning; SymbolCreator: a0412235
LOGO11 LOGO12 = CMP-0074837-1: IEC 61010-1 Hot Surface Warning; SymbolCreator: a0412235
ZZ1 = CMP-0003616-3
ZZ2 = CMP-0077236-1
ZZ3 = CMP-0077237-1
ZZ4 = CMP-0077238-1

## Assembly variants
001: not fitted D2 FID1 FID2 FID3 FID4 FID5 FID6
